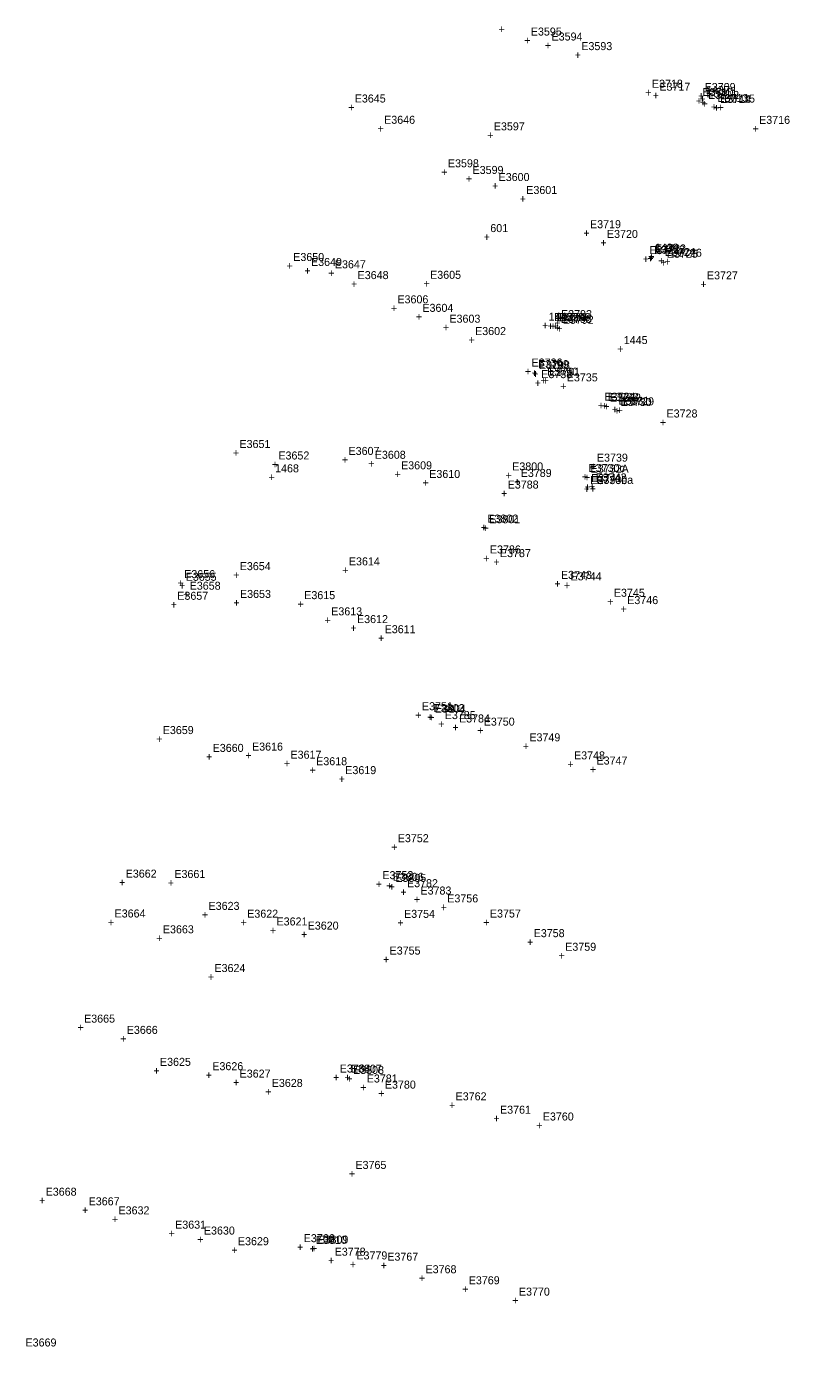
# Model space of a CAD drawing. Extents: x 1667192 to 1669644, y 336680 to 339991.
# Drawn here: x 1667244.7 to 1667483.1, y 337921.4 to 338333.8 of the extents above; entities that cross this region are included whole.
import ezdxf

# ---------------------------------------------------------------- set-up
doc = ezdxf.new("R2010")
doc.units = 0
for name, color, linetype in [('S_Control_Geodetic_ControlPoint', 7, 'Continuous'), ('S_Control_Temp_Traverse', 7, 'Continuous'), ('S_Curb_Type_5', 7, 'Continuous'), ('S_Drainage_CB', 7, 'Continuous'), ('S_Ground_Elevation', 7, 'Continuous'), ('S_Misc_MiscItems', 7, 'Continuous'), ('S_Property_IronPipeFound', 7, 'Continuous'), ('S_Property_StoneWall', 7, 'Continuous'), ('S_Roadway_Edge_Pavement', 7, 'Continuous'), ('S_Roadway_Edge_TW', 7, 'Continuous'), ('S_Roadway_Monument', 7, 'Continuous'), ('S_Traffic_Sign_SinglePost', 7, 'Continuous'), ('S_Utilities_GuyWire3', 7, 'Continuous'), ('S_Utilities_Pole_Power', 7, 'Continuous'), ('S_Utilities_Pole_StreetLight', 7, 'Continuous')]:
    doc.layers.add(name, color=color, linetype=linetype)

msp = doc.modelspace()

# ---------------------------------------------------------------- texts
at = {"layer": 'S_Control_Geodetic_ControlPoint'}
for s, p in [('1468', (1667322.4, 338194.48)), ('1468', (1667322.4, 338194.48)), ('+', (1667320.34, 338191.73)), ('+', (1667320.34, 338191.73))]:
    msp.add_text(s, height=2.5, dxfattribs=at).set_placement(p)
at = {"layer": 'S_Control_Temp_Traverse'}
for s, p in [('601', (1667389.62, 338269.53)), ('601', (1667389.62, 338269.53)), ('601', (1667389.62, 338269.53)), ('601', (1667389.62, 338269.53)), ('601', (1667389.62, 338269.53)), ('601', (1667389.62, 338269.53)), ('+', (1667387.56, 338266.78)), ('+', (1667387.56, 338266.78)), ('+', (1667387.56, 338266.78)), ('+', (1667387.56, 338266.78)), ('+', (1667387.56, 338266.78)), ('+', (1667387.56, 338266.78))]:
    msp.add_text(s, height=2.5, dxfattribs=at).set_placement(p)
at = {"layer": 'S_Curb_Type_5'}
for s, p in [('E3712', (1667457.65, 338311.13)), ('E3713', (1667460.57, 338310.17)), ('+', (1667455.59, 338308.38)), ('+', (1667458.51, 338307.42)), ('E3723', (1667441.06, 338263.17)), ('+', (1667439, 338260.42)), ('+', (1667442.05, 338259.33)), ('E3724', (1667444.11, 338262.08)), ('+', (1667408.19, 338238.93)), ('+', (1667409.09, 338238.98)), ('+', (1667409.6, 338238.4)), ('E3797', (1667410.25, 338241.68)), ('E3796', (1667411.16, 338241.73)), ('E3795', (1667411.66, 338241.15)), ('E3798', (1667404.81, 338226.75)), ('+', (1667402.75, 338224)), ('+', (1667405.32, 338221.94)), ('E3790', (1667407.38, 338224.69)), ('+', (1667424.92, 338213.83)), ('E3732', (1667426.98, 338216.58)), ('E3731', (1667429.6, 338215.61)), ('+', (1667427.54, 338212.86)), ('E3789', (1667399.11, 338193.05)), ('E3732A', (1667420.94, 338194.41)), ('+', (1667397.04, 338190.3)), ('+', (1667418.88, 338191.66)), ('+', (1667420.46, 338188.9)), ('E3741', (1667421.07, 338191.43)), ('E3742', (1667422.52, 338191.65)), ('+', (1667419.01, 338188.68)), ('E3801', (1667389.27, 338178.58)), ('+', (1667387.21, 338175.83)), ('E3804', (1667372.27, 338119.44)), ('+', (1667370.21, 338116.69)), ('E3805', (1667359.94, 338066.55)), ('+', (1667357.87, 338063.8)), ('+', (1667344.68, 338003.8)), ('E3808', (1667346.74, 338006.55)), ('E3809', (1667335.61, 337953.57)), ('+', (1667333.55, 337950.82))]:
    msp.add_text(s, height=2.5, dxfattribs=at).set_placement(p)
at = {"layer": 'S_Drainage_CB'}
for s, p in [('E3709', (1667456.57, 338313.61)), ('+', (1667454.51, 338310.86)), ('+', (1667405.78, 338239.12)), ('1443', (1667407.85, 338241.87)), ('E3752', (1667360.71, 338078.95)), ('+', (1667358.65, 338076.2))]:
    msp.add_text(s, height=2.5, dxfattribs=at).set_placement(p)
at = {"layer": 'S_Ground_Elevation'}
for s, p in [('+', (1667392.21, 338331.69)), ('E3595', (1667402.27, 338330.93)), ('+', (1667400.21, 338328.18)), ('E3645', (1667347.27, 338310.02)), ('+', (1667345.21, 338307.27)), ('+', (1667354.39, 338300.62)), ('E3646', (1667356.45, 338303.37)), ('E3598', (1667376.37, 338289.78)), ('E3599', (1667384.07, 338287.7)), ('+', (1667374.3, 338287.03)), ('+', (1667382.01, 338284.95)), ('E3650', (1667328.06, 338260.5)), ('+', (1667326, 338257.75)), ('+', (1667339, 338255.48)), ('E3647', (1667341.06, 338258.23)), ('E3606', (1667360.6, 338247.28)), ('+', (1667358.54, 338244.53)), ('E3604', (1667368.41, 338244.62)), ('+', (1667366.35, 338241.87)), ('E3651', (1667311.26, 338202.09)), ('+', (1667309.2, 338199.34)), ('E3652', (1667323.42, 338198.5)), ('+', (1667343.27, 338197.17)), ('E3607', (1667345.33, 338199.92)), ('E3608', (1667353.53, 338198.72)), ('+', (1667321.36, 338195.75)), ('+', (1667351.47, 338195.97)), ('E3800', (1667396.46, 338195.08)), ('+', (1667394.4, 338192.33)), ('E3786', (1667389.48, 338169.15)), ('+', (1667387.42, 338166.4)), ('E3658', (1667295.71, 338157.82)), ('+', (1667293.65, 338155.07)), ('+', (1667309.37, 338152.5)), ('E3653', (1667311.43, 338155.25)), ('+', (1667329.43, 338152.12)), ('E3615', (1667331.5, 338154.87)), ('E3613', (1667339.92, 338149.81)), ('+', (1667337.86, 338147.06)), ('+', (1667373.33, 338114.65)), ('E3785', (1667375.39, 338117.4)), ('E3659', (1667287.3, 338112.72)), ('+', (1667285.24, 338109.97)), ('E3660', (1667302.89, 338107.15)), ('E3616', (1667315.19, 338107.56)), ('+', (1667300.83, 338104.4)), ('+', (1667313.13, 338104.81)), ('+', (1667325.14, 338102.28)), ('E3617', (1667327.2, 338105.03)), ('+', (1667273.65, 338065.13)), ('E3662', (1667275.72, 338067.88)), ('E3661', (1667290.93, 338067.76)), ('E3782', (1667363.59, 338064.89)), ('+', (1667288.87, 338065.01)), ('+', (1667361.53, 338062.14)), ('E3623', (1667301.61, 338057.8)), ('+', (1667299.55, 338055.05)), ('E3622', (1667313.68, 338055.36)), ('+', (1667311.62, 338052.61)), ('+', (1667260.67, 338019.83)), ('E3665', (1667262.73, 338022.58)), ('+', (1667274, 338016.31)), ('E3666', (1667276.06, 338019.06)), ('E3625', (1667286.43, 338009.08)), ('E3626', (1667302.78, 338007.72)), ('+', (1667284.37, 338006.33)), ('+', (1667300.72, 338004.97)), ('E3781', (1667351.02, 338003.88)), ('+', (1667348.96, 338001.13)), ('E3668', (1667250.72, 337968.51)), ('+', (1667248.66, 337965.76)), ('+', (1667262.09, 337962.77)), ('E3667', (1667264.15, 337965.52)), ('E3632', (1667273.48, 337962.68)), ('+', (1667271.41, 337959.93)), ('E3631', (1667291.17, 337958.22)), ('+', (1667289.11, 337955.47)), ('E3778', (1667341, 337949.78)), ('+', (1667338.94, 337947.03)), ('E3669', (1667244.44, 337921.41))]:
    msp.add_text(s, height=2.5, dxfattribs=at).set_placement(p)
at = {"layer": 'S_Misc_MiscItems'}
for s, p in [('E3788', (1667395.04, 338189.42)), ('+', (1667392.98, 338186.67))]:
    msp.add_text(s, height=2.5, dxfattribs=at).set_placement(p)
at = {"layer": 'S_Property_IronPipeFound'}
for s, p in [('E3656', (1667293.99, 338161.45)), ('+', (1667291.93, 338158.7))]:
    msp.add_text(s, height=2.5, dxfattribs=at).set_placement(p)
at = {"layer": 'S_Property_StoneWall'}
for s, p in [('E3654', (1667311.35, 338163.93)), ('E3655', (1667294.46, 338160.6)), ('+', (1667309.29, 338161.18)), ('+', (1667292.4, 338157.85))]:
    msp.add_text(s, height=2.5, dxfattribs=at).set_placement(p)
at = {"layer": 'S_Roadway_Edge_Pavement'}
for s, p in [('E3594', (1667408.74, 338329.38)), ('+', (1667406.68, 338326.64)), ('1437', (1667456.99, 338312.67)), ('+', (1667454.93, 338309.92)), ('+', (1667455.05, 338308.85)), ('E3711', (1667457.11, 338311.6)), ('E3714', (1667461.36, 338309.88)), ('+', (1667459.3, 338307.13)), ('E3600', (1667392.21, 338285.48)), ('+', (1667390.15, 338282.73)), ('E3722', (1667440.74, 338262.81)), ('1439', (1667441.02, 338263.44)), ('+', (1667438.68, 338260.06)), ('+', (1667438.96, 338260.69)), ('E3725', (1667444.78, 338261.52)), ('+', (1667442.72, 338258.77)), ('E3793', (1667411.71, 338242.68)), ('+', (1667374.78, 338238.48)), ('E3603', (1667376.84, 338241.23)), ('+', (1667407.45, 338238.98)), ('E3794', (1667409.51, 338241.73)), ('+', (1667409.65, 338239.93)), ('E3792', (1667412.24, 338240.89)), ('+', (1667410.18, 338238.14)), ('1445', (1667431.31, 338234.56)), ('+', (1667429.25, 338231.81)), ('E3799', (1667404.51, 338227.04)), ('+', (1667402.45, 338224.29)), ('+', (1667405.95, 338221.89)), ('E3791', (1667408.01, 338224.64)), ('+', (1667424.28, 338214.04)), ('E3733', (1667426.34, 338216.79)), ('E3730', (1667430.32, 338215.21)), ('+', (1667428.25, 338212.46)), ('E3609', (1667361.74, 338195.43)), ('E3730c', (1667420.31, 338194.6)), ('+', (1667359.68, 338192.68)), ('+', (1667418.25, 338191.85)), ('E3730b', (1667420.84, 338190.81)), ('E3730a', (1667422.73, 338190.88)), ('+', (1667418.78, 338188.06)), ('+', (1667420.66, 338188.13)), ('E3802', (1667388.69, 338178.79)), ('+', (1667386.63, 338176.04)), ('E3787', (1667392.62, 338168)), ('+', (1667390.56, 338165.25)), ('E3612', (1667347.98, 338147.39)), ('+', (1667345.91, 338144.64)), ('E3803', (1667371.91, 338119.57)), ('+', (1667369.85, 338116.82)), ('E3784', (1667379.83, 338116.34)), ('+', (1667377.77, 338113.59)), ('E3618', (1667335.22, 338102.99)), ('+', (1667333.16, 338100.24)), ('E3806', (1667359.14, 338066.88)), ('+', (1667357.08, 338064.13)), ('E3783', (1667367.8, 338062.59)), ('+', (1667365.74, 338059.84)), ('E3621', (1667322.84, 338052.94)), ('+', (1667320.78, 338050.19)), ('E3627', (1667311.31, 338005.41)), ('+', (1667344.02, 338004.19)), ('E3807', (1667346.08, 338006.94)), ('+', (1667309.25, 338002.66)), ('+', (1667354.62, 337999.22)), ('E3780', (1667356.68, 338001.97)), ('E3630', (1667300.15, 337956.38)), ('E3810', (1667335.15, 337953.47)), ('+', (1667298.09, 337953.63)), ('+', (1667333.09, 337950.72)), ('+', (1667345.72, 337945.86)), ('E3779', (1667347.79, 337948.61))]:
    msp.add_text(s, height=2.5, dxfattribs=at).set_placement(p)
at = {"layer": 'S_Roadway_Edge_TW'}
for s, p in [('E3593', (1667418.04, 338326.38)), ('+', (1667415.98, 338323.63)), ('E3718', (1667440.09, 338314.63)), ('E3717', (1667442.42, 338313.71)), ('+', (1667438.03, 338311.88)), ('+', (1667440.36, 338310.96)), ('+', (1667453.81, 338309.3)), ('E3710', (1667455.87, 338312.05)), ('E3715', (1667462.63, 338309.99)), ('+', (1667460.57, 338307.24)), ('+', (1667471.52, 338300.6)), ('E3716', (1667473.58, 338303.35)), ('E3601', (1667400.85, 338281.43)), ('+', (1667398.79, 338278.68)), ('+', (1667418.69, 338268)), ('E3719', (1667420.76, 338270.75)), ('E3720', (1667426.05, 338267.71)), ('+', (1667423.99, 338264.96)), ('E3721', (1667439.29, 338262.66)), ('+', (1667437.23, 338259.91)), ('+', (1667443.96, 338259.09)), ('E3726', (1667446.03, 338261.84)), ('E3727', (1667457.28, 338254.77)), ('+', (1667455.22, 338252.02)), ('+', (1667382.8, 338234.62)), ('E3602', (1667384.86, 338237.37)), ('E3736', (1667402.5, 338227.54)), ('+', (1667400.44, 338224.79)), ('E3735', (1667413.5, 338222.9)), ('+', (1667411.44, 338220.15)), ('+', (1667423.2, 338214.12)), ('E3734', (1667425.26, 338216.87)), ('E3729', (1667431.1, 338215.41)), ('+', (1667429.03, 338212.66)), ('E3728', (1667444.66, 338211.62)), ('+', (1667442.6, 338208.87)), ('E3610', (1667370.54, 338192.73)), ('+', (1667368.48, 338189.98)), ('E3743', (1667411.69, 338161.2)), ('E3744', (1667414.69, 338160.73)), ('+', (1667409.63, 338158.45)), ('+', (1667412.62, 338157.98)), ('E3745', (1667428.2, 338155.62)), ('+', (1667426.14, 338152.87)), ('E3746', (1667432.38, 338153.32)), ('+', (1667430.32, 338150.57)), ('E3611', (1667356.61, 338144.23)), ('+', (1667354.54, 338141.48)), ('E3751', (1667368.26, 338120.18)), ('+', (1667366.19, 338117.43)), ('E3750', (1667387.56, 338115.36)), ('+', (1667385.5, 338112.61)), ('E3749', (1667401.82, 338110.46)), ('+', (1667399.76, 338107.71)), ('E3748', (1667415.77, 338104.82)), ('E3747', (1667422.79, 338103.21)), ('E3619', (1667344.31, 338100.21)), ('+', (1667413.71, 338102.07)), ('+', (1667420.72, 338100.46)), ('+', (1667342.25, 338097.46)), ('E3753', (1667355.9, 338067.4)), ('+', (1667353.84, 338064.65)), ('+', (1667374.11, 338057.39)), ('E3756', (1667376.17, 338060.14)), ('E3757', (1667389.49, 338055.42)), ('+', (1667330.51, 338048.89)), ('E3620', (1667332.57, 338051.64)), ('+', (1667387.43, 338052.67)), ('E3758', (1667403.16, 338049.28)), ('+', (1667401.1, 338046.53)), ('E3759', (1667413.01, 338045.03)), ('+', (1667410.95, 338042.28)), ('E3764', (1667342.57, 338007)), ('+', (1667340.51, 338004.25)), ('+', (1667319.29, 337999.74)), ('E3628', (1667321.35, 338002.49)), ('+', (1667376.71, 337995.56)), ('E3762', (1667378.77, 337998.31)), ('+', (1667390.59, 337991.38)), ('E3761', (1667392.65, 337994.13)), ('E3760', (1667406.01, 337992.01)), ('+', (1667403.95, 337989.27)), ('E3766', (1667331.32, 337954)), ('+', (1667308.72, 337950.3)), ('E3629', (1667310.78, 337953.05)), ('+', (1667329.26, 337951.25)), ('E3767', (1667357.44, 337948.23)), ('+', (1667355.38, 337945.48)), ('+', (1667367.32, 337941.54)), ('E3768', (1667369.38, 337944.29)), ('+', (1667380.82, 337938.09)), ('E3769', (1667382.88, 337940.84)), ('E3770', (1667398.55, 337937.3)), ('+', (1667396.49, 337934.55))]:
    msp.add_text(s, height=2.5, dxfattribs=at).set_placement(p)
at = {"layer": 'S_Roadway_Monument'}
for s, p in [('+', (1667289.78, 338151.92)), ('E3657', (1667291.84, 338154.67))]:
    msp.add_text(s, height=2.5, dxfattribs=at).set_placement(p)
at = {"layer": 'S_Traffic_Sign_SinglePost'}
for s, p in [('E3605', (1667370.81, 338254.94)), ('+', (1667368.75, 338252.19)), ('E3738', (1667405.54, 338223.91)), ('+', (1667403.48, 338221.16)), ('E3739', (1667422.91, 338197.83)), ('+', (1667420.85, 338195.08)), ('E3754', (1667362.67, 338055.31)), ('+', (1667360.61, 338052.56)), ('E3624', (1667303.45, 338038.38)), ('+', (1667301.39, 338035.63)), ('E3765', (1667347.49, 337976.88)), ('+', (1667345.43, 337974.13))]:
    msp.add_text(s, height=2.5, dxfattribs=at).set_placement(p)
at = {"layer": 'S_Utilities_GuyWire3'}
for s, p in [('E3649', (1667333.61, 338258.95)), ('+', (1667331.55, 338256.2)), ('E3664', (1667272.25, 338055.43)), ('+', (1667270.19, 338052.68))]:
    msp.add_text(s, height=2.5, dxfattribs=at).set_placement(p)
at = {"layer": 'S_Utilities_Pole_Power'}
for s, p in [('E3648', (1667348.17, 338254.85)), ('+', (1667346.1, 338252.1)), ('E3663', (1667287.34, 338050.48)), ('+', (1667285.27, 338047.73))]:
    msp.add_text(s, height=2.5, dxfattribs=at).set_placement(p)
at = {"layer": 'S_Utilities_Pole_StreetLight'}
for s, p in [('E3597', (1667390.71, 338301.32)), ('+', (1667388.65, 338298.57)), ('E3614', (1667345.44, 338165.42)), ('+', (1667343.38, 338162.67)), ('+', (1667356.1, 338041.09)), ('E3755', (1667358.16, 338043.84))]:
    msp.add_text(s, height=2.5, dxfattribs=at).set_placement(p)

doc.saveas('drawing.dxf')
